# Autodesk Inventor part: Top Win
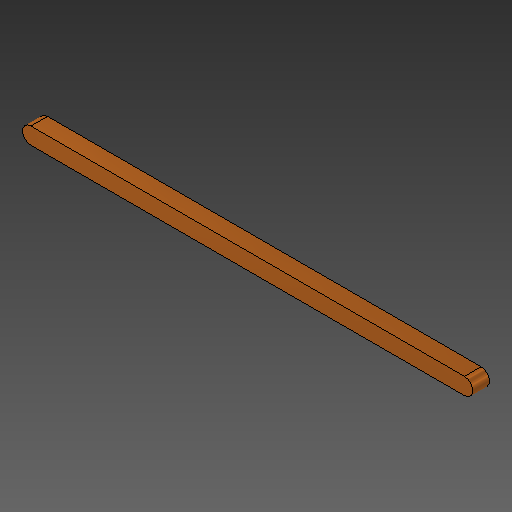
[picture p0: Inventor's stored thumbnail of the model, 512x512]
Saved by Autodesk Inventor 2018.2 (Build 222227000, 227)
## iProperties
Created: 2018-03
Part Number: Top Win
Material: Gold
Document SubType Name: Modeling
Designer: PeterMaxwell-Stewart
Mass: 64.6198 g
Surface Area: 27.1781 cm^2
Volume: 3.34817 cm^3
Density: 19.3 g/cm^3
Appearance: Metal 1600F Hot
Author: PeterMaxwell-Stewart
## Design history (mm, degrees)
derived "O's and X's.ipt"
feature "Top Win::O's and X's.ipt" dims "d0" = 10
tag "TaggingFeature1"
body "Solid1"
